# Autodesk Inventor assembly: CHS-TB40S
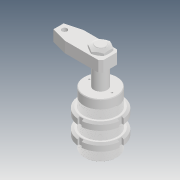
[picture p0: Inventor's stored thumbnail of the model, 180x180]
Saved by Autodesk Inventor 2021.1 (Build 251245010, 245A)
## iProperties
Created: 2019-04
Part Number: CHS-TB40S
Description: STEP AP203
Document SubType Name: Assembly
Designer: user
Title: chs-tb40s_asm.STEP
Revision Number: ÈÎºÎ
Sending System: SolidWorks 2017
Preprocessor: SwSTEP 2.0
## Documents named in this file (6)
- D:\Vault_2016\Projekty\Clamptek\Hydraulic\CHS\CHS-40\Inventor\CHS-TB40S\CHS-TB40S.iam
- D:\Vault_2016\Projekty\Clamptek\Hydraulic\CHS\CHS-40\Inventor\CHS-TB40S\CHS-TB40-03_1.ipt
- D:\Vault_2016\Projekty\Clamptek\Hydraulic\CHS\CHS-40\Inventor\CHS-TB40S\CHS-TB40-04_1.ipt
- D:\Vault_2016\Projekty\Clamptek\Hydraulic\CHS\CHS-40\Inventor\CHS-TB40S\CHS-40S-02_6.ipt
- D:\Vault_2016\Projekty\Clamptek\Hydraulic\CHS\CHS-40\Inventor\CHS-TB40S\CHS-40S-01_7.ipt
- D:\Vault_2016\Projekty\Clamptek\Hydraulic\CHS\CHS-40\Inventor\CHS-TB40S\M18_7.ipt
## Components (6 placed, 6 different names)
1. CHS-TB40-03_1_1
2. CHS-TB40-04_1_2
3. CHS-TB40-04_1_3
4. CHS-40S-02_6_4
5. CHS-40S-01_7_5
6. M18_7_6
